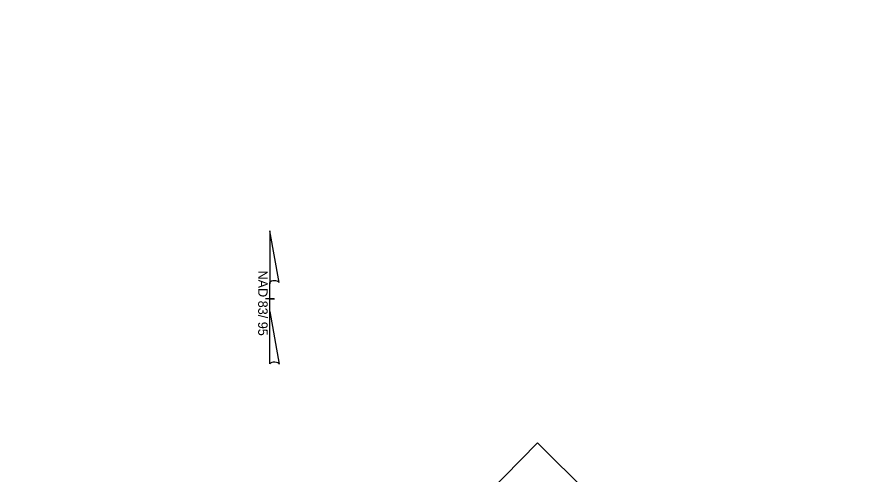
# Model space of a CAD drawing. Extents: x 1602193 to 1605074, y 908180 to 910630.
# Drawn here: x 1602900 to 1603654, y 910009 to 910420 of the extents above; entities that cross this region are included whole.
import ezdxf

# ---------------------------------------------------------------- set-up
doc = ezdxf.new("R2010")
doc.units = 0
for name, color, linetype in [('Prop Cable Guiderail Double Face', 7, 'Continuous'), ('Prop Dimension Text', 7, 'Continuous'), ('Prop EOT', 7, 'Continuous'), ('Prop Fence Woven Wire', 7, 'Continuous'), ('Prop Lane Lines', 7, 'Continuous'), ('Prop North Arrow NAD83 for Plan Sheets CELL', 7, 'Continuous'), ('Prop Paved Shoulder', 7, 'Continuous')]:
    doc.layers.add(name, color=color, linetype=linetype)

msp = doc.modelspace()

# ---------------------------------------------------------------- linework, layer by layer
at = {"layer": 'Prop Cable Guiderail Double Face'}
msp.add_arc((1613646.31, 919202), 14354.86, 219.580763, 222.768936, dxfattribs=at)
at = {"layer": 'Prop Dimension Text'}
for p, q in [((1603188.56, 909854.76), (1603368.87, 910036.95)), ((1603368.87, 910036.95), (1603651.42, 909757.33))]:
    msp.add_line(p, q, dxfattribs=at)
at = {"layer": 'Prop EOT'}
for radius, start, end in [(14311.86, 219.480877, 227.661141), (14335.86, 219.480979, 227.66104), (14381.86, 219.480979, 227.66104), (14405.86, 219.479716, 227.662303)]:
    msp.add_arc((1613646.31, 919202), radius, start, end, dxfattribs=at)
at = {"layer": 'Prop Fence Woven Wire'}
msp.add_arc((1613597.21, 919158.4), 14163.95, 218.093461, 222.076817, dxfattribs=at)
at = {"layer": 'Prop Lane Lines'}
for radius in [14323.86, 14393.86]:
    msp.add_arc((1613646.31, 919202), radius, 219.480979, 227.66104, dxfattribs=at)
at = {"layer": 'Prop North Arrow NAD83 for Plan Sheets CELL'}
for p, q in [((1603127.82, 910227.55), (1603127.87, 910227.55)), ((1603127.82, 910227.55), (1603127.87, 910227.55)), ((1603127.82, 910227.55), (1603127.84, 910179.75)), ((1603136.09, 910181.2), (1603127.87, 910227.55)), ((1603127.85, 910154.95), (1603127.84, 910181.15)), ((1603127.84, 910179.75), (1603127.84, 910181.1)), ((1603131.8, 910166.55), (1603123.8, 910166.55)), ((1603128.3, 910166.55), (1603131.85, 910166.55)), ((1603131.85, 910166.55), (1603131.9, 910166.55)), ((1603127.82, 910107.9), (1603127.85, 910154.95)), ((1603127.85, 910154.95), (1603136.22, 910107.7))]:
    msp.add_line(p, q, dxfattribs=at)
for centre, start_param, end_param in [((1603131.96, 910180.7), 3.374967, 6.066798), ((1603131.99, 910107.53), 3.141593, 6.081857)]:
    msp.add_ellipse(centre, major_axis=(-4.23, -0.03), ratio=0.461098, start_param=start_param, end_param=end_param, dxfattribs=at)
at = {"layer": 'Prop Paved Shoulder'}
for radius, start, end in [(14299.86, 219.480979, 223.794464), (14339.86, 219.480979, 222.863015), (14377.86, 219.48119, 222.373049), (14417.86, 219.480979, 222.382421)]:
    msp.add_arc((1613646.31, 919202), radius, start, end, dxfattribs=at)

# ---------------------------------------------------------------- texts
at = {"layer": 'Prop North Arrow NAD83 for Plan Sheets CELL'}
msp.add_text('NAD 83/ 95', height=8.5, rotation=270.02394, dxfattribs=at).set_placement((1603117.32, 910191.89))

doc.saveas('drawing.dxf')
